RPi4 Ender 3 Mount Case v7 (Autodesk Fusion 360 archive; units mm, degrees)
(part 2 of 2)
sketch "Skizze9" plane through (0, 0, 1) normal (0, 0, 1) x axis (1, 0, 0)
  line L1 (52.4999, 24.6406) -> (52.4999, -25)
  line L2 (-29.5, 28) -> (49.5215, 28)
  line L3 (-29.5, -28) -> (49.4999, -28)
  line L4 (-32.5, -25.0196) -> (-32.5, 24.5)
  line L5 (-32.5, 24.5) -> (-32.5, 25)
  line L6 (52.4999, 24.6406) -> (52.4999, -25)
  line L7 (-29.5, 28) -> (49.5215, 28)
  line L8 (-32.5, -25) -> (-32.5, 25)
  line L9 (49.4999, -28) -> (-29.5, -28)
  line L10 (-25.8, -29.25) -> (-16.8, -29.25)
  line L11 (-25.8, -21.75) -> (-25.8, -29.25)
  line L12 (-16.8, -21.75) -> (-25.8, -21.75)
  line L13 (-16.8, -29.25) -> (-16.8, -21.75)
  line L14 (-25.8, -21.75) -> (-16.8, -29.25)
  line L15 (-16.8, -21.75) -> (-25.8, -29.25)
  line L16 (-10.05, -29.3) -> (-2.95, -29.3)
  line L17 (-10.05, -21.3) -> (-10.05, -29.3)
  line L18 (-2.95, -21.3) -> (-10.05, -21.3)
  line L19 (-2.95, -29.3) -> (-2.95, -21.3)
  line L20 (-10.05, -21.3) -> (-2.95, -29.3)
  line L21 (-2.95, -21.3) -> (-10.05, -29.3)
  line L22 (3.45, -29.3) -> (10.55, -29.3)
  line L23 (3.45, -21.3) -> (3.45, -29.3)
  line L24 (10.55, -21.3) -> (3.45, -21.3)
  line L25 (10.55, -29.3) -> (10.55, -21.3)
  line L26 (3.45, -21.3) -> (10.55, -29.3)
  line L27 (10.55, -21.3) -> (3.45, -29.3)
  line L28 (25, -28) -> (18, -28)
  line L29 (25, -16.5) -> (25, -28)
  line L30 (18, -16.5) -> (25, -16.5)
  line L31 (18, -28) -> (18, -16.5)
  line L32 (25, -16.5) -> (18, -28)
  line L33 (18, -16.5) -> (25, -28)
  line L34 (37.9999, -26.35) -> (55.4999, -26.35)
  line L35 (37.9999, -11.65) -> (37.9999, -26.35)
  line L36 (55.4999, -11.65) -> (37.9999, -11.65)
  line L37 (55.4999, -26.35) -> (55.4999, -11.65)
  line L38 (37.9999, -11.65) -> (55.4999, -26.35)
  line L39 (55.4999, -11.65) -> (37.9999, -26.35)
  line L40 (37.9999, -8.35) -> (55.4999, -8.35)
  line L41 (37.9999, 6.35) -> (37.9999, -8.35)
  line L42 (55.4999, 6.35) -> (37.9999, 6.35)
  line L43 (55.4999, -8.35) -> (55.4999, 6.35)
  line L44 (37.9999, 6.35) -> (55.4999, -8.35)
  line L45 (55.4999, 6.35) -> (37.9999, -8.35)
  line L46 (33.9999, 9.75) -> (55.4999, 9.75)
  line L47 (33.9999, 25.75) -> (33.9999, 9.75)
  line L48 (55.4999, 25.75) -> (33.9999, 25.75)
  line L49 (55.4999, 9.75) -> (55.4999, 25.75)
  line L50 (33.9999, 25.75) -> (55.4999, 9.75)
  line L51 (55.4999, 25.75) -> (33.9999, 9.75)
  line L52 (-25.4, 22) -> (25.4, 22)
  line L53 (-25.4, 27) -> (-25.4, 22)
  line L54 (25.4, 27) -> (-25.4, 27)
  line L55 (25.4, 22) -> (25.4, 27)
  line L56 (-25.4, 27) -> (25.4, 22)
  line L57 (25.4, 27) -> (-25.4, 22)
  line L58 (29, 24.5) -> (-29, 24.5)
  line L59 (-29.75, -11) -> (-27.25, -11)
  line L60 (-29.75, 11) -> (-29.75, -11)
  line L61 (-27.25, 11) -> (-29.75, 11)
  line L62 (-27.25, -11) -> (-27.25, 11)
  line L63 (-29.75, 11) -> (-27.25, -11)
  line L64 (-27.25, 11) -> (-29.75, -11)
  line L65 (-10.75, -3) -> (4.25, -3)
  line L66 (-10.75, 12) -> (-10.75, -3)
  line L67 (4.25, 12) -> (-10.75, 12)
  line L68 (4.25, -3) -> (4.25, 12)
  line L69 (-10.75, 12) -> (4.25, -3)
  line L70 (4.25, 12) -> (-10.75, -3)
  line L71 (12.75, -27.5) -> (15.25, -27.5)
  line L72 (12.75, -5.5) -> (12.75, -27.5)
  line L73 (15.25, -5.5) -> (12.75, -5.5)
  line L74 (15.25, -27.5) -> (15.25, -5.5)
  line L75 (12.75, -5.5) -> (15.25, -27.5)
  line L76 (15.25, -5.5) -> (12.75, -27.5)
  line L77 (-24.4, -8.625) -> (-16.6, -8.625)
  line L78 (-24.4, -6.375) -> (-24.4, -8.625)
  line L79 (-16.6, -6.375) -> (-24.4, -6.375)
  line L80 (-16.6, -8.625) -> (-16.6, -6.375)
  line L81 (-24.4, -6.375) -> (-16.6, -8.625)
  line L82 (-16.6, -6.375) -> (-24.4, -8.625)
  line L83 (3.45, -29.3) -> (-2.95, -29.3)
  line L84 (3.45, -21.3) -> (-2.95, -21.3)
  line L85 (55.4999, -8.35) -> (55.4999, -11.65)
  line L86 (55.4999, 9.75) -> (55.4999, 6.35)
  line L87 (26.4, 15.76) -> (31.6, 15.76)
  line L88 (26.4, 20.96) -> (26.4, 15.76)
  line L89 (31.6, 20.96) -> (26.4, 20.96)
  line L90 (31.6, 15.76) -> (31.6, 20.96)
  line L91 (26.4, 20.96) -> (31.6, 15.76)
  line L92 (31.6, 20.96) -> (26.4, 15.76)
  line L93 (29, 18.36) -> (29, 24.5)
  line L94 (52.4999, 0) -> (-32.5, 0)
  line L95 (29, -24.5) -> (-29, -24.5)
  arc A1 centre (49.5215, 25) radius 3 clockwise from (49.5215, 28) to (52.4999, 24.6406)
  arc A2 centre (49.4999, -25) radius 3 clockwise from (52.4999, -25) to (49.4999, -28)
  circle C1 centre (29, -24.5) radius 1.3
  arc A3 centre (-29.5, 25) radius 3 clockwise from (-32.5, 25) to (-29.5, 28)
  arc A4 centre (-29.5, -25) radius 3 clockwise from (-29.5, -28) to (-32.5, -25)
  circle C2 centre (29, 24.5) radius 1.3
  circle C3 centre (-29, 24.5) radius 1.3
  circle C4 centre (-29, -24.5) radius 1.3
  circle C5 centre (29, -24.5) radius 1.3
  circle C6 centre (29, 24.5) radius 1.3
  circle C7 centre (-29, -24.5) radius 1.3
  circle C8 centre (-29, 24.5) radius 1.3
  arc A5 centre (49.4999, -25) radius 3 clockwise from (52.4999, -25) to (49.4999, -28)
  arc A6 centre (49.5215, 25) radius 3 clockwise from (49.5215, 28) to (52.4999, 24.6406)
  arc A7 centre (-29.5, 25) radius 3 clockwise from (-32.5, 25) to (-29.5, 28)
  arc A8 centre (-29.5, -25) radius 3 clockwise from (-29.5, -28) to (-32.5, -25)
  point P48 (-21.3, -25.5)
  point P53 (-6.5, -25.3)
  point P58 (7, -25.3)
  point P63 (21.5, -22.25)
  point P60 (25, -28)
  point P68 (46.7499, -19)
  point P73 (46.7499, -1)
  point P78 (44.7499, 17.75)
  point P83 (0, 24.5)
  point P24 (-29, 24.5)
  point P84 (-29, 24.5)
  point P23 (29, 24.5)
  point P85 (29, 24.5)
  point P90 (-28.5, 0)
  point P95 (-3.25, 4.5)
  point P100 (14, -16.5)
  point P105 (-20.5, -7.5)
  point P110 (29, 18.36)
  point P29 (29, 24.5)
  point P111 (29, 24.5)
  point P112 (29, 18.36)
  point P113 (-32.5, 0)
  point P114 (52.4999, 0)
  point P25 (-29, -24.5)
  point P115 (-29, -24.5)
  point P28 (29, -24.5)
  point P116 (29, -24.5)
  point P66 (37.9999, -11.65)
  point P67 (55.4999, -11.65)
  point P64 (55.4999, -26.35)
  point P61 (25, -16.5)
  point P62 (18, -16.5)
  point P76 (33.9999, 25.75)
  point P77 (55.4999, 25.75)
  point P75 (33.9999, 9.75)
  point P107 (26.4, 15.76)
  point P108 (26.4, 20.96)
  point P109 (31.6, 20.96)
  point P69 (55.4999, -8.35)
  point P70 (37.9999, -8.35)
  point P72 (55.4999, 6.35)
  point P44 (-16.8, -29.25)
  point P45 (-25.8, -29.25)
  point P47 (-16.8, -21.75)
  point P96 (15.25, -27.5)
  point P99 (15.25, -5.5)
  point P98 (12.75, -5.5)
  point P93 (-10.75, 12)
  point P94 (4.25, 12)
  point P79 (25.4, 22)
  point P82 (25.4, 27)
  point P81 (-25.4, 27)
  point P103 (-24.4, -6.375)
  point P104 (-16.6, -6.375)
  point P101 (-16.6, -8.625)
  point P88 (-29.75, 11)
  point P89 (-27.25, 11)
  point P86 (-27.25, -11)
  perpendicular L10 L11
  parallel L10 L12
  parallel L11 L13
  horizontal L10
  coincident L14 P48
  coincident L15 P48
  perpendicular L16 L17
  parallel L16 L18
  parallel L17 L19
  horizontal L16
  coincident L20 P53
  coincident L21 P53
  perpendicular L22 L23
  parallel L22 L24
  parallel L23 L25
  horizontal L22
  coincident L26 P58
  coincident L27 P58
  perpendicular L28 L29
  parallel L28 L30
  parallel L29 L31
  horizontal L28
  coincident L32 P63
  coincident L33 P63
  coincident L3 P60
  perpendicular L34 L35
  parallel L34 L36
  parallel L35 L37
  horizontal L34
  coincident L38 P68
  coincident L39 P68
  perpendicular L40 L41
  parallel L40 L42
  parallel L41 L43
  horizontal L40
  coincident L44 P73
  coincident L45 P73
  perpendicular L46 L47
  parallel L46 L48
  parallel L47 L49
  horizontal L46
  coincident L50 P78
  coincident L51 P78
  perpendicular L52 L53
  parallel L52 L54
  parallel L53 L55
  horizontal L52
  coincident L56 P83
  coincident L57 P83
  coincident P24 P84
  coincident P23 P85
  coincident P83 L58
  perpendicular L59 L60
  parallel L59 L61
  parallel L60 L62
  horizontal L59
  coincident L63 P90
  coincident L64 P90
  perpendicular L65 L66
  parallel L65 L67
  parallel L66 L68
  horizontal L65
  coincident L69 P95
  coincident L70 P95
  perpendicular L71 L72
  parallel L71 L73
  parallel L72 L74
  horizontal L71
  coincident L75 P100
  coincident L76 P100
  perpendicular L77 L78
  parallel L77 L79
  parallel L78 L80
  horizontal L77
  coincident L81 P105
  coincident L82 P105
  horizontal L83
  horizontal L84
  perpendicular L42 L86
  vertical L85
  perpendicular L87 L88
  parallel L87 L89
  parallel L88 L90
  horizontal L87
  coincident L91 P110
  coincident L92 P110
  midpoint L70 P95
  coincident P29 P111
  coincident P110 P112
  vertical L93
  equal L67 L68
  coincident L8 P113
  coincident L1 P114
  horizontal L94
  coincident P25 P115
  coincident P28 P116
  symmetric L58 L94 L95
  coincident P90 L94
  dimension "d66" distance L3 P68 = 9
  dimension "d67" distance L3 P73 = 27
  dimension "d68" distance L3 P78 = 45.75
  dimension "d69" distance P83 P84 = 29
  dimension "d70" distance P25 P48 = 7.7
  dimension "d71" distance P48 P53 = 14.8
  dimension "d72" distance P53 P58 = 13.5
  dimension "d73" distance L17 L19 = 7.1
  dimension "d74" distance L23 L25 = 7.1
  dimension "d75" distance L16 L18 = 8
  dimension "d76" distance P66 P67 = 17.5
  dimension "d77" distance P64 P67 = 14.7
  dimension "d78" distance L3 L22 = 1.3
  dimension "d79" distance P60 P61 = 11.5
  dimension "d80" distance P61 P62 = 7
  dimension "d82" distance P58 P100 = 7
  dimension "d84" distance P63 P100 = 7.5
  dimension "d85" distance L1 L85 = 3
  dimension "d86" distance P76 P77 = 21.5
  dimension "d87" distance P75 P76 = 16
  dimension "d88" distance P107 P108 = 5.2
  dimension "d89" distance P108 P109 = 5.2
  dimension "d90" distance L3 P100 = 11.5
  dimension "d91" distance P69 P70 = 17.5 (= "d76")
  dimension "d92" distance P69 P72 = 14.7 (= "d77")
  dimension "d122" distance L4 P105 = 12
  dimension "d123" distance L3 P105 = 20.5
  dimension "d124" distance L4 P90 = 4
  dimension "d125" distance L3 P95 = 32.5
  dimension "d126" distance P84 P95 = 25.75
  dimension "d127" distance L3 L10 = 1.25
  dimension "d128" distance P44 P45 = 9
  dimension "d129" distance P44 P47 = 7.5
  dimension "d130" distance P96 P99 = 22
  dimension "d131" distance P98 P99 = 2.5
  dimension "d133" distance L58 P110 = 6.14
  dimension "d134" distance P93 P94 = 15
  dimension "d137" distance P79 P82 = 5
  dimension "d138" distance P81 P82 = 50.8
  dimension "d139" distance P103 P104 = 7.8
  dimension "d140" distance P101 P104 = 2.25
  dimension "d141" distance P88 P89 = 2.5
  dimension "d142" distance P86 P89 = 22
extrude "Extrusion8" new body sketch "Skizze9" profile of L9 L10 L11 L12 L13 along normal blind 3.2 bodies "Power USB C"
extrude "Extrusion9" new body sketch "Skizze9" profile of L9 L16 L17 L18 L19 L22 L23 L24 L25 along normal blind 3.3 bodies "Micro HDMI 1", "Micro HDMI 2"
extrude "Extrusion10" new body sketch "Skizze9" profile of L59 L60 L61 L62 L71 L72 L73 L74 along normal blind 5.5 bodies "Kamera", "Display"
extrude "Extrusion11" new body sketch "Skizze9" profile of L9 L28 L29 L30 L31 along normal blind 6 bodies "3.5 mm Audio"
extrude "Extrusion12" new body sketch "Skizze9" profile of A5 L6 L34 L35 L36 L37 L40 L41 L42 L43 along normal blind 16.5 bodies "USB 2.0", "USB 3.0"
extrude "Extrusion13" new body sketch "Skizze9" profile of A1 L6 A6 L46 L47 L48 L49 along normal blind 13.5 bodies "Ethernet"
extrude "Extrusion14" new body sketch "Skizze9" profile of L52 L53 L54 L55 L87 L88 L89 L90 along normal blind 8.5 bodies "GPIO 40", "PoE"
extrude "Extrusion15" new body sketch "Skizze9" profile of L65 L66 L67 L68 along normal blind 2.4 bodies "Processor"
sketch "Skizze10" plane through (0, -28, 0) normal (0, -1, 0) x axis (1, 0, 0)
  line L1 (25, 1) -> (18, 1)
  line L2 (25, 7) -> (25, 1)
  line L3 (18, 7) -> (25, 7)
  line L4 (18, 1) -> (18, 7)
  line L5 (25, 1) -> (18, 7)
  line L6 (18, 1) -> (25, 7)
  circle C1 centre (21.5, 4) radius 3
  point P5 (18, 7)
  point P7 (18, 7)
  point P3 (25, 1)
  point P8 (25, 1)
  point P4 (25, 7)
  point P9 (25, 7)
  point P2 (18, 1)
  point P10 (18, 1)
  point P6 (21.5, 4)
  tangent L1 C1
  coincident P5 P7
  coincident P3 P8
  coincident P4 P9
  coincident P2 P10
  coincident P6 L6
  coincident P6 L5
extrude "Extrusion16" add sketch "Skizze10" profile of C1 along normal blind 2.5
fillet "Abrundung1" radius 1.5
chamfer "Fase" distance 1
fillet "Abrundung2" radius 0.5
component_from_bodies "Körper->Berechn4"
component_from_bodies "Körper->Berechn5"
component_from_bodies "Körper->Berechn6"
component_from_bodies "Körper->Berechn7"
component_from_bodies "Körper->Berechn8"
component_from_bodies "Körper->Berechn9"
component_from_bodies "Körper->Berechn10"
component_from_bodies "Körper->Berechn11"
component_from_bodies "Körper->Berechn12"
component_from_bodies "Körper->Berechn13"
component_from_bodies "Körper->Berechn14"
component_from_bodies "Körper->Berechn15"
as_built_joint "Bestand"
ground "Fixieren"
sketch "Skizze11" plane through (0, 0, 0) normal (0, 0, -1) x axis (1, 0, 0)
  line L1 (-29.5, 28) -> (49.4985, 28)
  line L2 (-32.5, -25) -> (-32.5, 25)
  line L3 (49.4985, -28) -> (-29.5, -28)
  line L4 (52.4985, 25) -> (52.4985, -25)
  line L5 (-29, -24.5) -> (-29, 24.5)
  line L6 (-35, 5.5) -> (-23, 5.5)
  line L7 (-35, -5.5) -> (-35, 5.5)
  line L8 (-23, -5.5) -> (-35, -5.5)
  line L9 (-23, 5.5) -> (-23, -5.5)
  line L10 (-35, -5.5) -> (-23, 5.5)
  line L11 (-23, -5.5) -> (-35, 5.5)
  circle C1 centre (29, 24.5) radius 1.35
  circle C2 centre (-29, 24.5) radius 1.35
  circle C3 centre (-29, -24.5) radius 1.35
  circle C4 centre (29, -24.5) radius 1.35
  arc A1 centre (49.4985, 25) radius 3 clockwise from (49.4985, 28) to (52.4985, 25)
  arc A2 centre (-29.5, 25) radius 3 clockwise from (-32.5, 25) to (-29.5, 28)
  arc A3 centre (-29.5, -25) radius 3 clockwise from (-29.5, -28) to (-32.5, -25)
  arc A4 centre (49.4985, -25) radius 3 clockwise from (52.4985, -25) to (49.4985, -28)
  point P3 (-29, 24.5)
  point P18 (-29, 24.5)
  point P4 (-29, -24.5)
  point P19 (-29, -24.5)
  point P24 (-29, 0)
  point P21 (-35, 5.5)
  point P22 (-35, -5.5)
  point P23 (-23, -5.5)
  coincident P3 P18
  coincident P4 P19
  perpendicular L6 L7
  parallel L6 L8
  parallel L7 L9
  horizontal L6
  coincident L10 P24
  coincident L11 P24
  midpoint L5 P24
  dimension "d114" distance P21 P22 = 11
  dimension "d115" distance P22 P23 = 12
extrude "Extrusion1" new body sketch "Skizze11" profile of L2 L6 L7 L8 L9 along normal blind 1.2
fillet "Abrundung1" radius 0.6
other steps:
base_feature "Basiselement1" bodies "Power USB C"
base_feature "Basiselement1" bodies "Micro HDMI 2"
base_feature "Basiselement1" bodies "3.5 mm Audio"
base_feature "Basiselement1" bodies "Micro HDMI 1"
base_feature "Basiselement1" bodies "USB 2.0"
base_feature "Basiselement1" bodies "Display"
base_feature "Basiselement1" bodies "Processor"
base_feature "Basiselement1" bodies "Ethernet"
base_feature "Basiselement1" bodies "Kamera"
base_feature "Basiselement1" bodies "GPIO 40"
base_feature "Basiselement1" bodies "USB 3.0"
base_feature "Basiselement1" bodies "PoE"
base_feature "Basiselement1"
create_component "Komponente erstellen3"
remove_body "Körper entfernen3"
create_component "Komponente erstellen4"
remove_body "Körper entfernen4"
create_component "Komponente erstellen5"
remove_body "Körper entfernen5"
create_component "Komponente erstellen6"
remove_body "Körper entfernen6"
create_component "Komponente erstellen7"
remove_body "Körper entfernen7"
create_component "Komponente erstellen8"
remove_body "Körper entfernen8"
create_component "Komponente erstellen9"
remove_body "Körper entfernen9"
create_component "Komponente erstellen10"
remove_body "Körper entfernen10"
create_component "Komponente erstellen11"
remove_body "Körper entfernen11"
create_component "Komponente erstellen12"
remove_body "Körper entfernen12"
create_component "Komponente erstellen13"
remove_body "Körper entfernen13"
create_component "Komponente erstellen14"
remove_body "Körper entfernen14"
create_component "Komponente erstellen15"
remove_body "Körper entfernen15"
named bodies: "Power USB C", "Micro HDMI 1", "Micro HDMI 2", "Kamera", "Display", "3.5 mm Audio", "USB 2.0", "USB 3.0", "Ethernet", "GPIO 40", "PoE", "Processor"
